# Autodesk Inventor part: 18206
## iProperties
Created: 2007-10
Part Number: 18206
Material: 3.2315.71 AlMgSi1 F28
Description: Zentrierring (Al/FPM) DN 16 KF
Document SubType Name: Modellieren
Designer: TMT
Manufacturer: Standard
Standards Organization: Custom
Density: 1 g/cm^3
Vendor: LEYBOLD
Author: TMT
Comments: LEYBOLD
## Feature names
1. Extrusion2
2. Bohrung1 [Hole]
3. Umdrehung1 [Revolution]
4. Umdrehung2 [Revolution]
5. Fase1 [Chamfer]
